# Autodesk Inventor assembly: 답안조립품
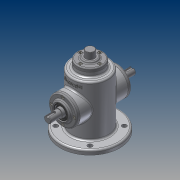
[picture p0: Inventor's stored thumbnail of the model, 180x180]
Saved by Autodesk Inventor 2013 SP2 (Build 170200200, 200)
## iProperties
Created: 2014-12
Part Number: 답안조립품
Document SubType Name: Assembly
Designer: CADB105
Author: CADB105
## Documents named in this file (12)
- C:\Users\CADB105\Desktop\441228V1014\답안조립품.iam
- C:\Users\CADB105\Desktop\441228V1014\441228V1014 본체.ipt
- C:\Users\CADB105\Desktop\441228V1014\441228V1014 편심축.ipt
- C:\Users\CADB105\Desktop\441228V1014\M3x0.5x8.ipt
- M3x0.5.ipt
- C:\Users\CADB105\Desktop\441228V1014\베어링 6002.ipt
- 베어링 6002.ipt
- C:\Users\CADB105\Desktop\441228V1014\상단커버.ipt
- C:\Users\CADB105\Desktop\441228V1014\슬라이드.ipt
- C:\Users\CADB105\Desktop\441228V1014\오일실.ipt
- 오일실.ipt
- C:\Users\CADB105\Desktop\441228V1014\커버.ipt
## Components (14 placed, 3 different names)
1. 441228V1014 본체:1 — 각도:1, 각도:2, 각도:3
2. 441228V1014 편심축:1 — 각도:1
3. M3x0.5:2 — 각도:2
4. M3x0.5:4
5. M3x0.5:5
6. M3x0.5:6
7. M3x0.5:3 — 각도:3
8. M3x0.5:7
9. M3x0.5:8
10. M3x0.5:9
11. M3x0.5:1 — 각도:4
12. M3x0.5:10
13. M3x0.5:11
14. M3x0.5:12
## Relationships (4: Angle 4)
- 각도:1 [Angle]: 441228V1014 본체:1 ↔ 441228V1014 편심축:1
- 각도:2 [Angle]: 441228V1014 본체:1 ↔ M3x0.5:2
- 각도:3 [Angle]: 441228V1014 본체:1 ↔ M3x0.5:3
- 각도:4 [Angle]: M3x0.5:1
